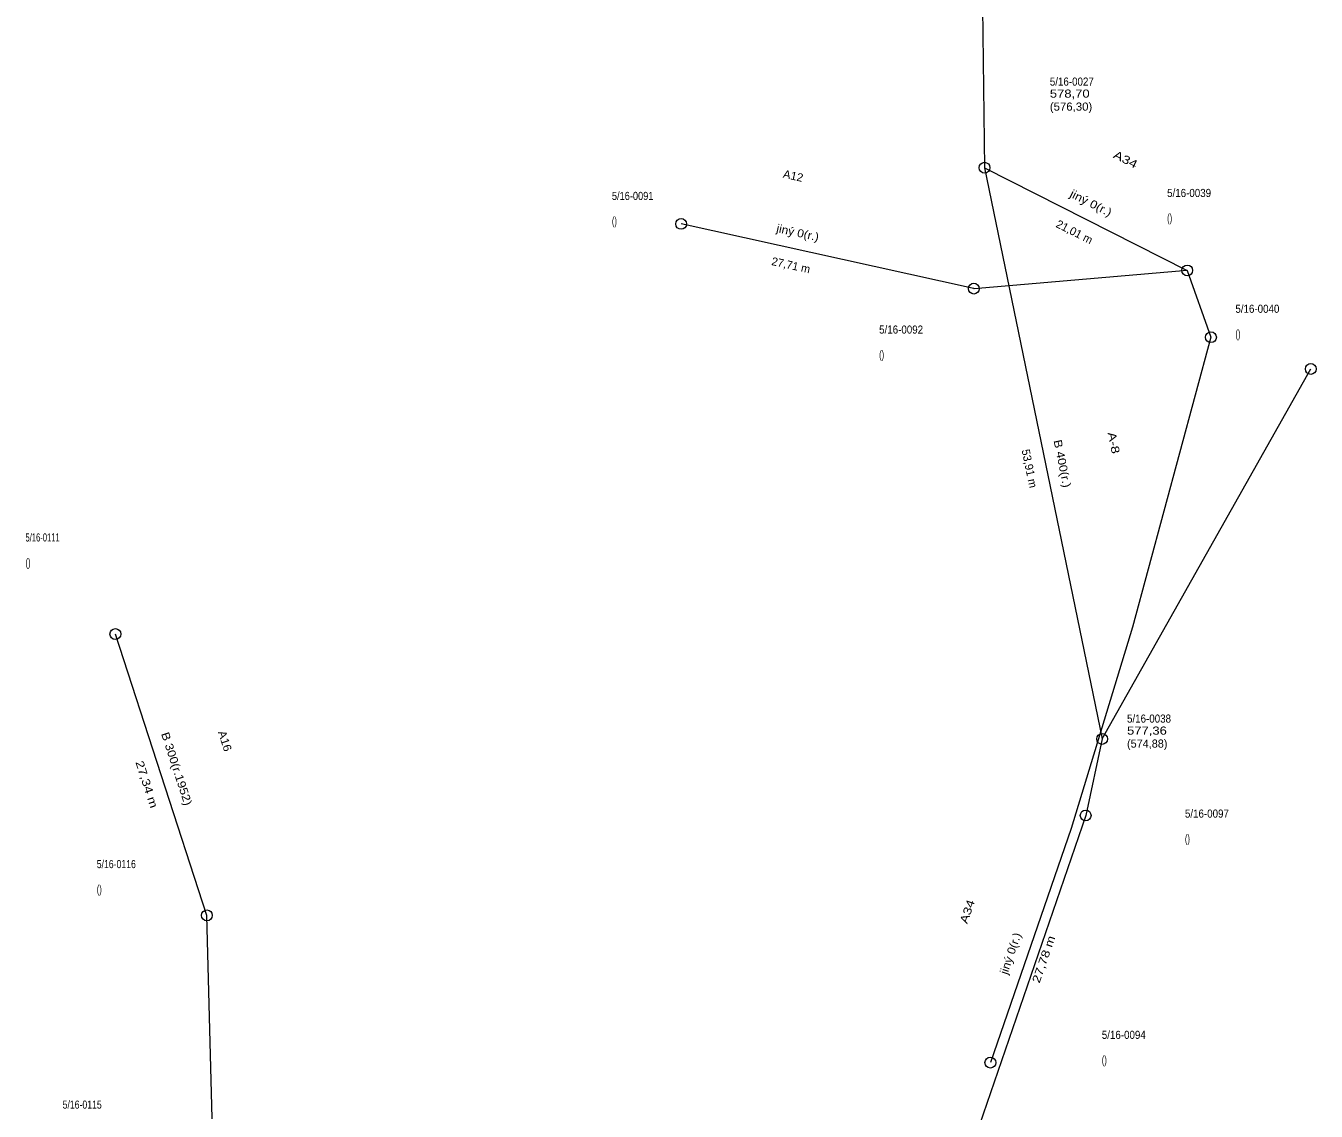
# Model space of a CAD drawing. Extents: x -710854 to -709799, y -1117012 to -1115891.
# Drawn here: x -710185.2 to -710065.9, y -1116198.3 to -1116098 of the extents above; entities that cross this region are included whole.
import ezdxf
from ezdxf.enums import TextEntityAlignment as Align

# ---------------------------------------------------------------- set-up
doc = ezdxf.new("R2010")
doc.units = 0
doc.header["$LTSCALE"] = 0.3
doc.layers.add('38', color=7, linetype='Continuous', lineweight=13)
doc.layers.add('44', color=7, linetype='Continuous', lineweight=13)
doc.layers.add('48', color=7, linetype='Continuous')

msp = doc.modelspace()

# ---------------------------------------------------------------- linework, layer by layer
at = {"layer": '38'}
for p, q in [((-710096.531, -1116111.108), (-710085.659, -1116163.906)), ((-710085.659, -1116163.906), (-710066.37, -1116129.71)), ((-710085.659, -1116163.906), (-710087.18, -1116170.98))]:
    msp.add_line(p, q, dxfattribs=at)
for points in [[(-710097.338, -1116047.014), (-710096.531, -1116111.108), (-710077.79, -1116120.6)], [(-710097.52, -1116122.283), (-710097.685, -1116122.247), (-710124.58, -1116116.3)], [(-710077.79, -1116120.6), (-710097.49, -1116122.29), (-710097.52, -1116122.283)], [(-710077.79, -1116120.6), (-710075.596, -1116126.762), (-710075.6, -1116126.776)], [(-710075.6, -1116126.776), (-710082.864, -1116153.588), (-710088.514, -1116172.172), (-710095.992, -1116193.825)], [(-710168.42, -1116180.213), (-710168.42, -1116180.21), (-710176.88, -1116154.21)], [(-710087.18, -1116170.98), (-710109.55, -1116236.05), (-710109.565, -1116236.081)], [(-710167.93, -1116199.034), (-710167.931, -1116198.992), (-710168.42, -1116180.213)]]:
    msp.add_lwpolyline(points, dxfattribs=at)
at = {"layer": '44'}
for centre in [(-710096.531, -1116111.108), (-710124.58, -1116116.3), (-710077.79, -1116120.6), (-710097.52, -1116122.283), (-710075.6, -1116126.776), (-710066.37, -1116129.71), (-710176.88, -1116154.21), (-710085.659, -1116163.906), (-710087.18, -1116170.98), (-710168.42, -1116180.213), (-710095.992, -1116193.825)]:
    msp.add_circle(centre, 0.5, dxfattribs=at)

# ---------------------------------------------------------------- texts
at = {"layer": '48'}
for s, width, p in [('5/16-0027', 0.9, (-710090.494, -1116103.522)), ('578,70 ', 1.2, (-710090.494, -1116104.632)), ('(576,30)', 1.05, (-710090.494, -1116105.832)), ('5/16-0091', 0.85, (-710130.979, -1116114.089)), ('5/16-0039', 0.9, (-710079.652, -1116113.815)), ('()', 0.7, (-710079.652, -1116116.125)), ('()', 0.7, (-710130.979, -1116116.399)), ('5/16-0040', 0.9, (-710073.339, -1116124.52)), ('5/16-0092', 0.9, (-710106.276, -1116126.441)), ('()', 0.7, (-710073.339, -1116126.83)), ('()', 0.7, (-710106.276, -1116128.751)), ('5/16-0111', 0.7, (-710185.189, -1116145.654)), ('()', 0.7, (-710185.189, -1116147.965)), ('5/16-0038', 0.9, (-710083.357, -1116162.398)), ('577,36 ', 1.2, (-710083.357, -1116163.508)), ('5/16-0097', 0.9, (-710078.005, -1116171.181)), ('()', 0.7, (-710078.005, -1116173.491)), ('5/16-0116', 0.8, (-710178.601, -1116175.847)), ('()', 0.7, (-710178.601, -1116178.157)), ('5/16-0094', 0.9, (-710085.69, -1116191.63)), ('()', 0.7, (-710085.69, -1116193.94)), ('5/16-0115', 0.8, (-710181.758, -1116198.08))]:
    msp.add_text(s, height=0.75, dxfattribs=dict(at, width=width)).set_placement(p)
for s, rotation, width, p in [('A34', 333.14, 1.3, (-710083.6639, -1116110.6757)), ('A12', 347.53, 1.05, (-710114.2995, -1116112.2227)), ('jiný 0(r.)', 333.14, 1.15, (-710086.8604, -1116114.7055)), ('jiný 0(r.)', 347.53, 1.1, (-710113.8805, -1116117.4766)), ('A-8', 281.64, 1.3, (-710084.9496, -1116136.6088)), ('B 400(r.)', 281.64, 1.15, (-710089.7003, -1116138.5293)), ('B 300(r.1952)', 288.02, 1.15, (-710171.5707, -1116166.779)), ('A16', 288.02, 1.1, (-710167.1065, -1116164.207)), ('27,34 m', 288.02, 1.25, (-710174.3312, -1116168.215)), ('A34', 70.95, 1.25, (-710097.7727, -1116179.9864)), ('jiný 0(r.)', 70.95, 1.1, (-710093.7754, -1116183.8539)), ('27,78 m', 70.95, 1.25, (-710090.7126, -1116184.3869))]:
    msp.add_text(s, height=0.75, rotation=rotation, dxfattribs=dict(at, width=width)).set_placement(p, align=Align.CENTER)
for s, rotation, p in [('21,01 m', 333.14, (-710088.3829, -1116117.3762)), ('27,71 m', 347.53, (-710114.505, -1116120.4832)), ('53,91 m', 281.64, (-710092.7402, -1116138.9863))]:
    msp.add_text(s, height=0.75, rotation=rotation, dxfattribs=at).set_placement(p, align=Align.CENTER)
msp.add_text('(574,88)', height=0.75, dxfattribs=at).set_placement((-710083.357, -1116164.708))

doc.saveas('drawing.dxf')
